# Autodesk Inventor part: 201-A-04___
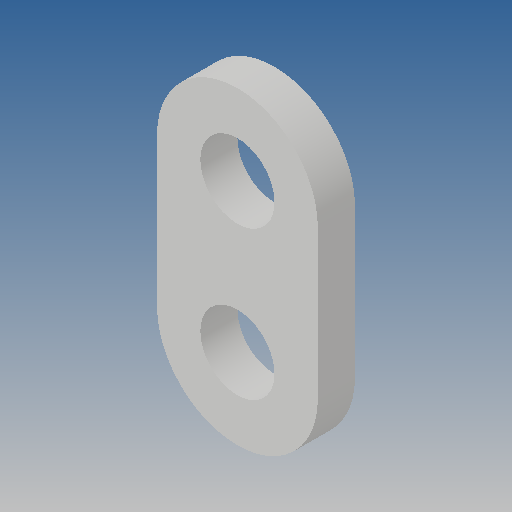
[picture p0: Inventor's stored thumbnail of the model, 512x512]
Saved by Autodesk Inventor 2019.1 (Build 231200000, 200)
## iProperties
Created: 2010-06
Part Number: 201-A-04___
Material: Ogólny
Document SubType Name: Modeling
Designer: CADENGINEERING4
Density: 1 g/cm^3
Appearance: Domyślna
Author: CADENGINEERING4
Revision Number: ANY
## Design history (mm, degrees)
feature "NONE"
node "Bryła1"
